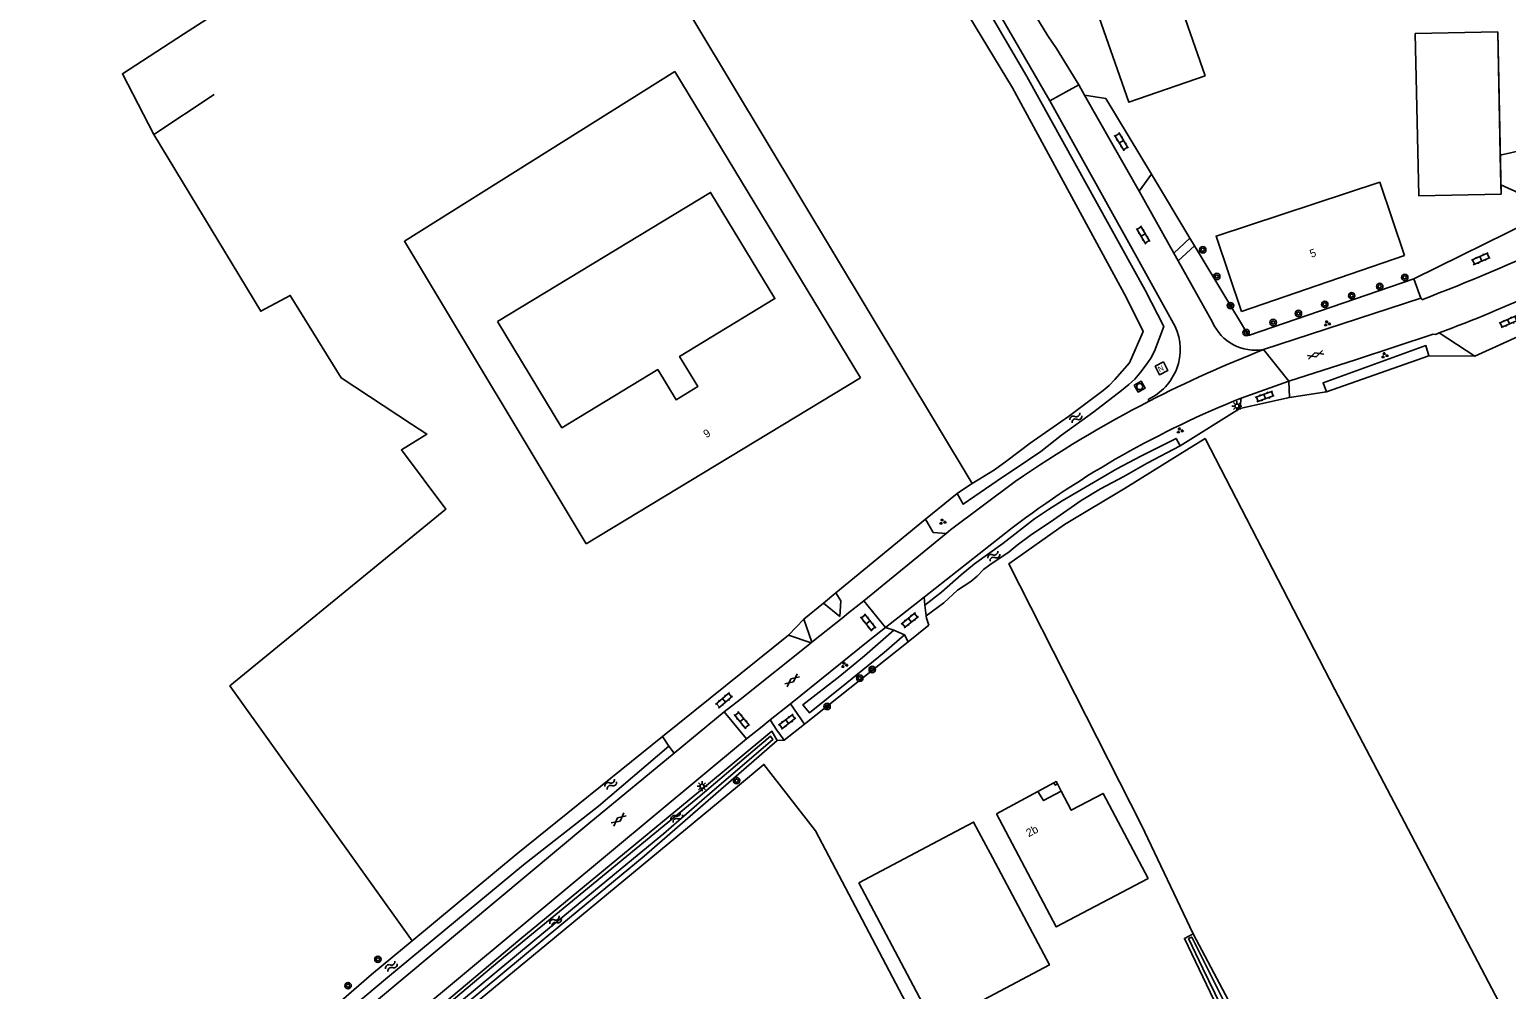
# Model space of a CAD drawing. Extents: x 135999 to 138000, y 396000 to 398501.
# Drawn here: x 136699.2 to 136883.8, y 396981.4 to 397101.4 of the extents above; entities that cross this region are included whole.
import ezdxf

# ---------------------------------------------------------------- set-up
doc = ezdxf.new("R2010")
doc.units = 0
for name, color, linetype in [('gg-afsc-draadraster', 7, 'Continuous'), ('gg-afsc-hekwerk', 7, 'Continuous'), ('gg-afsc-lijn draadraster', 7, 'Continuous'), ('gg-afsc-muur', 7, 'Continuous'), ('gg-anno-huisnummerreeks BGT', 7, 'Continuous'), ('gg-bbg-bijgebouw', 7, 'Continuous'), ('gg-bbg-gedigitaliseerde bebouwing', 7, 'Continuous'), ('gg-bbg-gedigitaliseerde bijgebouw', 7, 'Continuous'), ('gg-bbg-hoofdgebouw', 7, 'Continuous'), ('gg-bbg-onder overbouw', 7, 'Continuous'), ('gg-bbg-pand overbouw', 7, 'Continuous'), ('gg-bbg-pilaar onder overbouw', 7, 'Continuous'), ('gg-bbg-pilaar pand', 7, 'Continuous'), ('gg-knt-bronhoudergrens', 7, 'Continuous'), ('gg-knt-onverhard', 7, 'Continuous'), ('gg-knt-verharding', 7, 'Continuous'), ('gg-knt-verharding nz', 7, 'Continuous'), ('gg-kntw-bovenkant insteek waterloop', 7, 'Continuous'), ('gg-kntw-waterlijn', 7, 'Continuous'), ('gt-grn-groengrens', 7, 'Continuous'), ('gt-grn-vlakafsluiter', 7, 'Continuous'), ('gt-grn-weggrens', 7, 'Continuous'), ('gt-symb-boom', 7, 'Continuous'), ('gt-symb-gesloten verharding', 7, 'Continuous'), ('gt-symb-groenvak', 7, 'Continuous'), ('gt-symb-klinker verharding', 7, 'Continuous'), ('gt-symb-lichtmast', 7, 'Continuous'), ('gt-symb-nortonput', 7, 'Continuous'), ('gt-symb-rioolschacht', 7, 'Continuous'), ('gt-symb-watersymbool', 7, 'Continuous'), ('gx-grn-BAG pand plantopografie verbouwing', 7, 'Continuous'), ('gx-grn-maaiveld', 7, 'Continuous')]:
    doc.layers.add(name, color=color, linetype=linetype)

# ---------------------------------------------------------------- blocks, each defined once
blk = doc.blocks.new('gt0-KL1')
at = {"layer": 'gt-symb-klinker verharding'}
for p, q in [((-1.15, 0.3), (1.15, 0.3)), ((-1, -0.3), (-1, 0.3)), ((-0.5, 0.3), (-0.5, 0.45)), ((0, -0.3), (0, 0.3)), ((0.5, 0.3), (0.5, 0.45)), ((1, -0.3), (1, 0.3)), ((-1.15, -0.3), (1.15, -0.3)), ((-0.5, -0.45), (-0.5, -0.3)), ((0.5, -0.45), (0.5, -0.3))]:
    blk.add_line(p, q, dxfattribs=at)
blk = doc.blocks.new('gt0-BOOM')
at = {"layer": 'gt-symb-boom'}
for radius in [0.4, 0.2]:
    blk.add_circle((0, 0), radius, dxfattribs=at)
blk = doc.blocks.new('gt0-RS')
at = {"layer": 'gt-symb-rioolschacht'}
blk.add_lwpolyline([(-0.5, -0.5), (0.5, -0.5), (0.5, 0.5), (-0.5, 0.5)], close=True, dxfattribs=at)
blk.add_circle((0, 0), 0.375, dxfattribs=at)
blk = doc.blocks.new('gt0-NPUT')
at = {"layer": 'gt-symb-nortonput'}
blk.add_lwpolyline([(-0.57, -0.61), (-0.57, 0.59), (0.63, 0.59), (0.63, -0.61)], close=True, dxfattribs=at)
blk.add_text('N', height=0.7, dxfattribs=at).set_placement((-0.22, -0.38))
blk = doc.blocks.new('gt0-GESVH1')
at = {"layer": 'gt-symb-gesloten verharding'}
for p, q in [((-0.99, -0.26), (0.01, 0.24)), ((0.01, -0.26), (-0.99, 0.24)), ((0.01, 0.24), (1.01, -0.26)), ((1.01, 0.24), (0.01, -0.26))]:
    blk.add_line(p, q, dxfattribs=at)
blk = doc.blocks.new('gt0-GRVAK')
at = {"layer": 'gt-symb-groenvak'}
for p, q in [((-0.11, 0.19), (-0.23, 0.24)), ((-0.18, 0.15), (0.09, 0.15)), ((-0.09, 0.21), (-0.16, 0.32)), ((-0.05, 0.21), (-0.05, 0.39)), ((0, 0.21), (0.06, 0.32)), ((0.02, 0.19), (0.13, 0.24)), ((0.26, -0.05), (0.2, 0.06)), ((0.3, -0.05), (0.3, 0.13)), ((0.35, -0.05), (0.41, 0.06)), ((-0.24, -0.23), (-0.36, -0.18)), ((-0.32, -0.26), (-0.05, -0.26)), ((-0.23, -0.21), (-0.29, -0.1)), ((-0.18, -0.2), (-0.18, -0.02)), ((-0.14, -0.21), (-0.07, -0.1)), ((-0.12, -0.23), (0, -0.18)), ((0.24, -0.07), (0.12, -0.02)), ((0.17, -0.11), (0.44, -0.11)), ((0.37, -0.07), (0.49, -0.02))]:
    blk.add_line(p, q, dxfattribs=at)
blk = doc.blocks.new('gt0-WA')
at = {"layer": 'gt-symb-watersymbool'}
for centre, start, end in [((-0.32, 0.02), 28.0725, 151.9275), ((0.43, 0.42), 208.0725, 331.9275), ((-0.32, -0.43), 28.0725, 151.9275), ((0.43, -0.03), 208.0725, 331.9275)]:
    blk.add_arc(centre, 0.425, start, end, dxfattribs=at)
blk = doc.blocks.new('gt0-LMAST')
at = {"layer": 'gt-symb-lichtmast'}
for p, q in [((-0.18, 0.17), (-0.45, 0.44)), ((-0.01, 0.25), (-0.01, 0.62)), ((0.17, 0.17), (0.44, 0.44)), ((-0.26, 0), (-0.63, 0)), ((-0.18, -0.18), (-0.45, -0.45)), ((-0.01, -0.25), (-0.01, -0.63)), ((0.44, -0.45), (0.17, -0.18)), ((0.24, 0), (0.62, 0))]:
    blk.add_line(p, q, dxfattribs=at)
blk.add_circle((-0.01, 0), 0.25, dxfattribs=at)

msp = doc.modelspace()

# ---------------------------------------------------------------- linework, layer by layer
at = {"layer": 'gg-afsc-draadraster'}
for points in [[(136842.96, 397048.32), (136836.15, 397044.09), (136828.54, 397039.55), (136821.58, 397034.63), (136838.19, 397001.98), (136844.64, 396988.38)], [(136787.67, 397006.79), (136763.83, 396987.1), (136739.79, 396967.26)]]:
    msp.add_lwpolyline(points, dxfattribs=at)
at = {"layer": 'gg-afsc-hekwerk'}
for p, q in [((136808.99, 397024.87), (136811.61, 397026.96)), ((136808.99, 397024.87), (136811.61, 397026.96)), ((136796.06, 397014.6), (136808.99, 397024.87)), ((136796.06, 397014.6), (136808.99, 397024.87)), ((136793.51, 397012.58), (136796.06, 397014.6)), ((136793.51, 397012.58), (136796.06, 397014.6))]:
    msp.add_line(p, q, dxfattribs=at)
at = {"layer": 'gg-afsc-lijn draadraster'}
msp.add_line((136883.71, 396978.2), (136862.33, 397018.93), dxfattribs=at)
for points in [[(136747.02, 396987.51), (136724.24, 397019.37), (136751.23, 397041.47), (136745.67, 397048.87), (136748.85, 397050.86), (136746.92, 397052.07), (136738.13, 397057.87), (136731.78, 397068.19), (136728.08, 397066.2), (136714.71, 397088.3), (136722.26, 397093.32)], [(136842.96, 397048.32), (136836.15, 397044.09), (136828.54, 397039.55), (136821.58, 397034.63), (136838.19, 397001.98), (136844.64, 396988.38)], [(136787.67, 397006.79), (136763.83, 396987.1), (136739.79, 396967.26)]]:
    msp.add_lwpolyline(points, dxfattribs=at)
at = {"layer": 'gg-afsc-muur'}
for p, q in [((136844.21, 397075.36), (136839.41, 397083.33)), ((136844.79, 397074.4), (136844.21, 397075.36)), ((136845.12, 397073.85), (136844.79, 397074.4))]:
    msp.add_line(p, q, dxfattribs=at)
at = {"layer": 'gg-bbg-bijgebouw'}
for p, q in [((136802.85, 396994.75), (136812.76, 397000)), ((136819.53, 396997.93), (136818.43, 397000))]:
    msp.add_line(p, q, dxfattribs=at)
for points in [[(136821.73, 397134.87), (136836.58, 397092.33), (136846.14, 397095.65)], [(136812.76, 397000), (136817.19, 397002.35), (136818.43, 397000)], [(136802.85, 396994.75), (136812.32, 396976.88), (136826.66, 396984.48), (136819.53, 396997.93)]]:
    msp.add_lwpolyline(points, dxfattribs=at)
at = {"layer": 'gg-bbg-gedigitaliseerde bebouwing'}
msp.add_line((136779.86, 397096.17), (136803.04, 397057.88), dxfattribs=at)
for points in [[(136768.76, 397037.15), (136746.04, 397074.96), (136779.86, 397096.17)], [(136757.67, 397064.94), (136765.72, 397051.65), (136777.71, 397058.91), (136779.99, 397055.15), (136782.72, 397056.8), (136780.44, 397060.57), (136792.36, 397067.79), (136784.31, 397081.07), (136757.67, 397064.94)], [(136871.04, 397073.17), (136867.96, 397082.33), (136847.5, 397075.61), (136850.66, 397066.18)], [(136839, 396995.31), (136827.52, 396989.24), (136820.03, 397003.38)]]:
    msp.add_lwpolyline(points, dxfattribs=at)
at = {"layer": 'gg-bbg-gedigitaliseerde bijgebouw'}
msp.add_lwpolyline([(136846.14, 397095.65), (136831.29, 397138.2), (136821.73, 397134.87)], dxfattribs=at)
at = {"layer": 'gg-bbg-hoofdgebouw'}
for p, q in [((136871.04, 397073.17), (136850.66, 397066.18)), ((136803.04, 397057.88), (136768.76, 397037.15)), ((136825.22, 397006.16), (136820.03, 397003.38))]:
    msp.add_line(p, q, dxfattribs=at)
msp.add_lwpolyline([(136839, 396995.31), (136833.38, 397005.92), (136829.4, 397003.83), (136828.13, 397006.23)], dxfattribs=at)
at = {"layer": 'gg-bbg-onder overbouw'}
msp.add_lwpolyline([(136828.13, 397006.23), (136825.93, 397005.04), (136825.22, 397006.16)], dxfattribs=at)
at = {"layer": 'gg-bbg-pand overbouw'}
for p, q in [((136827.23, 397007.25), (136825.22, 397006.16)), ((136827.67, 397007.12), (136828.13, 397006.23))]:
    msp.add_line(p, q, dxfattribs=at)
at = {"layer": 'gg-bbg-pilaar onder overbouw'}
msp.add_lwpolyline([(136827.23, 397007.25), (136827.39, 397006.97), (136827.67, 397007.12)], dxfattribs=at)
at = {"layer": 'gg-bbg-pilaar pand'}
msp.add_lwpolyline([(136827.67, 397007.12), (136827.52, 397007.4), (136827.23, 397007.25)], dxfattribs=at)
at = {"layer": 'gg-knt-bronhoudergrens'}
for p, q in [((136846.12, 397050.28), (136842.96, 397048.32)), ((136862.33, 397018.93), (136846.12, 397050.28))]:
    msp.add_line(p, q, dxfattribs=at)
msp.add_lwpolyline([(136815.4, 396967.75), (136812.15, 396973.03), (136809.55, 396978.2), (136797.44, 397001.25), (136790.97, 397009.55), (136787.67, 397006.79)], dxfattribs=at)
at = {"layer": 'gg-knt-onverhard'}
msp.add_line((136826.7, 397092.51), (136817.92, 397107.73), dxfattribs=at)
msp.add_lwpolyline([(136809.49, 397129.77), (136817.67, 397115.5), (136825.43, 397102.33), (136826.47, 397100.63), (136827.56, 397099.06), (136830.33, 397094.52)], dxfattribs=at)
at = {"layer": 'gg-knt-verharding'}
for p, q in [((136826.7, 397092.51), (136830.33, 397094.52)), ((136837.21, 397073.62), (136826.7, 397092.51)), ((136837.89, 397081.22), (136839.41, 397083.33)), ((136837.89, 397081.22), (136842.22, 397073.47)), ((136872.23, 397070.24), (136886.9, 397077.53)), ((136844.21, 397075.36), (136842.22, 397073.47)), ((136837.21, 397073.62), (136842.39, 397064.29)), ((136842.22, 397073.47), (136842.77, 397072.49)), ((136844.79, 397074.4), (136842.77, 397072.49)), ((136842.77, 397072.49), (136847.05, 397064.83)), ((136873.08, 397067.84), (136872.23, 397070.24)), ((136853.44, 397061.41), (136873.08, 397067.84)), ((136879.82, 397060.58), (136875.38, 397063.49)), ((136856.58, 397057.48), (136850.64, 397055.35)), ((136856.58, 397057.48), (136856.67, 397055.41)), ((136839.14, 397054.97), (136838.99, 397055.18)), ((136850.47, 397054.04), (136856.67, 397055.41)), ((136850.64, 397055.35), (136850.47, 397054.04)), ((136811.18, 397040.2), (136799.97, 397030.99)), ((136803.47, 397030.02), (136813.75, 397038.44)), ((136822.02, 397039.13), (136810.99, 397030.46)), ((136800.48, 397028.06), (136798.42, 397029.72)), ((136803.47, 397030.02), (136801.56, 397028.5)), ((136803.47, 397030.02), (136806.16, 397026.66)), ((136810.99, 397030.46), (136806.16, 397026.66)), ((136811.1, 397029.46), (136810.99, 397030.46)), ((136811.25, 397028.12), (136811.1, 397029.46)), ((136795.96, 397027.71), (136796.97, 397024.84)), ((136800.75, 397027.85), (136796.97, 397024.84)), ((136801.56, 397028.5), (136800.75, 397027.85)), ((136794.04, 397025.7), (136796.89, 397024.77)), ((136806.16, 397026.66), (136804.23, 397025.11)), ((136807.21, 397026.32), (136806.16, 397026.66)), ((136808.54, 397025.77), (136807.21, 397026.32)), ((136808.99, 397024.87), (136808.54, 397025.77)), ((136796.89, 397024.77), (136788, 397017.69)), ((136804.23, 397025.11), (136794.29, 397017.14)), ((136796.97, 397024.84), (136796.89, 397024.77)), ((136788, 397017.69), (136786.03, 397016.12)), ((136794.29, 397017.14), (136791.78, 397015.13)), ((136794.29, 397017.14), (136796.06, 397014.6)), ((136786.03, 397016.12), (136779.77, 397010.95)), ((136786.03, 397016.12), (136788.8, 397012.74)), ((136790.77, 397014.31), (136788.8, 397012.74)), ((136791.78, 397015.13), (136790.77, 397014.31)), ((136779.08, 397011.83), (136778.3, 397013.04)), ((136779.08, 397011.83), (136779.77, 397010.95))]:
    msp.add_line(p, q, dxfattribs=at)
for points in [[(136873.08, 397067.84), (136873.15, 397067.86), (136873.23, 397067.66)], [(136887.64, 397067.29), (136886.53, 397063.62), (136879.82, 397060.58)], [(136813.75, 397038.44), (136814.28, 397038.88), (136822.39, 397044.93)], [(136813.75, 397038.44), (136812.15, 397038.55), (136811.18, 397040.2)], [(136799.97, 397030.99), (136800.58, 397030.01), (136800.48, 397028.06)], [(136811.61, 397026.96), (136811.28, 397027.83), (136811.25, 397028.12)], [(136793.51, 397012.58), (136792.61, 397013.84), (136791.78, 397015.13)], [(136788.8, 397012.74), (136771.69, 396998.51), (136747.35, 396978.24)], [(136779.77, 397010.95), (136769.1, 397002.15), (136738.25, 396976.43), (136729.99, 396969.4), (136729.71, 396969.33), (136723.7, 396964.14), (136723.46, 396963.64), (136696.05, 396939.83)]]:
    msp.add_lwpolyline(points, dxfattribs=at)
for centre, radius, start, end in [((136789.38, 397288.34), 236.08, 290.8026, 295.3307), ((136817.01, 397220.7), 167.69, 290.3687, 295.0412), ((136836.14, 397061.44), 6.87, 294.527, 24.5554), ((136852.43, 397067.21), 5.88, 203.8681, 279.8464), ((136907.87, 396921.42), 150.2, 111.2469, 117.2316), ((136895.99, 396941.97), 122.11, 111.799, 127.2803), ((136907.91, 396921.33), 150.29, 117.2301, 124.6783)]:
    msp.add_arc(centre, radius, start, end, dxfattribs=at)
at = {"layer": 'gg-knt-verharding nz'}
for p, q in [((136830.33, 397094.52), (136831.06, 397093.24)), ((136831.06, 397093.24), (136837.89, 397081.22))]:
    msp.add_line(p, q, dxfattribs=at)
at = {"layer": 'gg-kntw-bovenkant insteek waterloop'}
for p, q in [((136760.03, 396998.29), (136778.3, 397013.04)), ((136760.03, 396998.29), (136747.21, 396987.67)), ((136747.21, 396987.67), (136747.02, 396987.51))]:
    msp.add_line(p, q, dxfattribs=at)
for points in [[(136798.83, 397132.34), (136801.28, 397133.82), (136812.55, 397114.88), (136823.86, 397095.54), (136838.62, 397068.83), (136840.95, 397064.28), (136839.79, 397061.23)], [(136839.79, 397061.23), (136839.33, 397060.35), (136838.77, 397059.52), (136837.98, 397058.46), (136837.33, 397057.71), (136836.61, 397057.03), (136835.69, 397056.29), (136832.22, 397053.64), (136828.19, 397050.71), (136825.58, 397048.69), (136823.94, 397047.55), (136820.12, 397045), (136815.9, 397042.07), (136815.12, 397043.44)], [(136817.02, 397044.66), (136819.79, 397046.39), (136821.36, 397047.49), (136824.27, 397049.7), (136829.04, 397053.03), (136833.4, 397056.28), (136834.15, 397056.93), (136834.85, 397057.66), (136836.66, 397059.74)], [(136811.1, 397029.46), (136813.16, 397031.08), (136815.65, 397033.27), (136817.32, 397034.65), (136820.85, 397037.17), (136824.79, 397040.24), (136826.56, 397041.44), (136828.26, 397042.49), (136835.1, 397046.49), (136838.1, 397048.1), (136842.49, 397050.3), (136843, 397049.4)], [(136843, 397049.4), (136838.88, 397047.23), (136835.96, 397045.56), (136833.03, 397044), (136830.65, 397042.54), (136827.19, 397040.12), (136824.24, 397038.17), (136822.64, 397036.97), (136821.64, 397036.11), (136819.21, 397034.52), (136818.42, 397033.94), (136817.63, 397033.09), (136816.83, 397032.44), (136815.19, 397031.35), (136813.46, 397029.75), (136811.25, 397028.12)], [(136815.12, 397043.44), (136816.43, 397044.3), (136817.02, 397044.66)], [(136808.54, 397025.77), (136805.99, 397023.56), (136801.36, 397019.75), (136796.66, 397016.01), (136795.85, 397017.01), (136800.45, 397020.6), (136803.55, 397023.13), (136807.21, 397026.32)], [(136743.58, 396971.21), (136765.71, 396989.58), (136776.02, 396998.1), (136792.64, 397012.56)], [(136792.64, 397012.56), (136791.98, 397013.7), (136783.07, 397006.28), (136760.46, 396987.68)], [(136760.94, 396996.98), (136770.3, 397004.35), (136779.08, 397011.83)], [(136727.74, 396970.97), (136728.47, 396969.94), (136743.91, 396982.93), (136760.94, 396996.98)], [(136747.02, 396987.51), (136741.94, 396983.31), (136727.74, 396970.97)], [(136760.46, 396987.68), (136742.44, 396972.51), (136743.58, 396971.21)], [(136844.64, 396988.38), (136843.53, 396987.81), (136847.22, 396980.11)]]:
    msp.add_lwpolyline(points, dxfattribs=at)
at = {"layer": 'gg-kntw-waterlijn'}
for points in [[(136743.18, 396972.59), (136757.71, 396984.84), (136782.71, 397005.37), (136791.8, 397013.09), (136792.08, 397012.66), (136784.17, 397005.86), (136778.43, 397000.86), (136773.26, 396996.63), (136762.28, 396987.52), (136743.61, 396972.03), (136743.18, 396972.59)], [(136862.69, 396949.06), (136863.06, 396949.53), (136862.81, 396950.43), (136861.45, 396953.32), (136860.21, 396955.56), (136849.53, 396976.4), (136845.85, 396984.06), (136844.06, 396987.78), (136844.46, 396987.97), (136848.9, 396979.11), (136855.53, 396965.92), (136862.53, 396952.68), (136863.75, 396950.01), (136863.65, 396949.17), (136862.95, 396948.38)]]:
    msp.add_lwpolyline(points, dxfattribs=at)
at = {"layer": 'gt-grn-groengrens'}
for p, q in [((136874.08, 397060.64), (136861.3, 397056.13)), ((136874.08, 397060.64), (136879.82, 397060.58)), ((136856.67, 397055.41), (136861.3, 397056.13)), ((136843, 397049.4), (136850.47, 397054.04)), ((136811.18, 397040.2), (136815.12, 397043.44)), ((136798.42, 397029.72), (136799.97, 397030.99)), ((136795.96, 397027.71), (136794.04, 397025.7)), ((136792.64, 397012.56), (136793.51, 397012.58))]:
    msp.add_line(p, q, dxfattribs=at)
for points in [[(136845.12, 397073.85), (136851.53, 397063.19), (136872.23, 397070.24)], [(136861.3, 397056.13), (136860.86, 397057.26), (136873.73, 397061.91), (136874.08, 397060.64)]]:
    msp.add_lwpolyline(points, dxfattribs=at)
at = {"layer": 'gt-grn-vlakafsluiter'}
msp.add_line((136794.04, 397025.7), (136778.3, 397013.04), dxfattribs=at)
at = {"layer": 'gt-grn-weggrens'}
for p, q in [((136833.72, 397092.8), (136831.06, 397093.24)), ((136839.41, 397083.33), (136833.72, 397092.8)), ((136856.58, 397057.48), (136853.44, 397061.41)), ((136795.96, 397027.71), (136798.42, 397029.72))]:
    msp.add_line(p, q, dxfattribs=at)
at = {"layer": 'gx-grn-BAG pand plantopografie verbouwing'}
msp.add_line((136883.12, 397080.86), (136882.7, 397101.15), dxfattribs=at)
at = {"layer": 'gx-grn-maaiveld'}
for p, q in [((136883.02, 397085.71), (136882.7, 397101.15)), ((136883.02, 397085.71), (136883.1, 397082.01)), ((136883.1, 397082.01), (136883.12, 397080.86)), ((136883.71, 396978.2), (136862.33, 397018.93)), ((136844.64, 396988.38), (136858.3, 396962.57))]:
    msp.add_line(p, q, dxfattribs=at)
for points in [[(136883.02, 397085.71), (136891.86, 397087.73), (136890.98, 397104.47), (136879.95, 397104.23), (136888.02, 397111.35), (136918.91, 397136.11), (136942.25, 397155.01), (136950.14, 397160.65)], [(136747.02, 396987.51), (136724.24, 397019.37), (136751.23, 397041.47), (136745.67, 397048.87), (136748.85, 397050.86), (136746.92, 397052.07), (136738.13, 397057.87), (136731.78, 397068.19), (136728.08, 397066.2), (136714.71, 397088.3), (136710.79, 397095.9), (136718.42, 397100.86), (136760.71, 397128.09), (136765.38, 397130.62), (136817.02, 397044.66)], [(136812.79, 397109.44), (136822.06, 397094.13), (136836.3, 397067.89), (136838.37, 397063.69), (136836.66, 397059.74)], [(136883.12, 397080.86), (136872.82, 397080.65), (136872.4, 397100.93), (136882.7, 397101.15)], [(136883.1, 397082.01), (136885.77, 397080.79), (136885.87, 397079.1), (136888.51, 397076.63)], [(136856.58, 397057.48), (136865.05, 397060.17), (136874.62, 397063.35), (136874.88, 397063.31)], [(136874.88, 397063.31), (136875.12, 397063.4), (136875.38, 397063.49)]]:
    msp.add_lwpolyline(points, dxfattribs=at)

# ---------------------------------------------------------------- block references
at = {"layer": 'gt-symb-boom'}
for p in [(136845.83, 397073.89), (136847.58, 397070.55), (136867.95, 397069.31), (136871.08, 397070.44), (136864.44, 397068.15), (136849.3, 397066.91), (136857.79, 397065.93), (136861.08, 397067.07), (136854.63, 397064.8), (136851.25, 397063.54), (136804.52, 397021.42), (136802.96, 397020.34), (136798.88, 397016.8), (136787.56, 397007.53), (136742.73, 396985.19), (136739, 396981.89)]:
    msp.add_blockref('gt0-BOOM', p, dxfattribs=at)
at = {"layer": 'gt-symb-gesloten verharding'}
for p, rotation in [((136859.92, 397060.76), 18.12681251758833), ((136794.5, 397020.06), 39.196688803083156), ((136772.82, 397002.67), 39.196688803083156)]:
    msp.add_blockref('gt0-GESVH1', p, dxfattribs=dict(at, rotation=rotation))
at = {"layer": 'gt-symb-groenvak'}
for p in [(136861.36, 397064.67), (136868.55, 397060.69), (136842.96, 397051.29), (136813.3, 397039.88), (136801.03, 397021.98)]:
    msp.add_blockref('gt0-GRVAK', p, dxfattribs=at)
at = {"layer": 'gt-symb-klinker verharding'}
for p, rotation in [((136835.66, 397087.41), -58.918270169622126), ((136838.38, 397075.74), -58.99693247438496), ((136880.58, 397072.76), 23.386642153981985), ((136884.06, 397064.9), -156.17710051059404), ((136853.57, 397055.55), -159.75249849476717), ((136804.01, 397027.3), 128.25701687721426), ((136809.22, 397027.58), 38.5434627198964), ((136785.99, 397017.57), 40.53915174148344), ((136788.23, 397015.1), -50.64204308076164), ((136793.89, 397014.9), 37.31697448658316)]:
    msp.add_blockref('gt0-KL1', p, dxfattribs=dict(at, rotation=rotation))
at = {"layer": 'gt-symb-lichtmast'}
for p in [(136850.11, 397054.36), (136783.25, 397006.82)]:
    msp.add_blockref('gt0-LMAST', p, dxfattribs=at)
at = {"layer": 'gt-symb-nortonput', "rotation": -153.1274610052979}
msp.add_blockref('gt0-NPUT', (136840.7, 397059.07), dxfattribs=at)
at = {"layer": 'gt-symb-rioolschacht', "rotation": -60.66720921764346}
msp.add_blockref('gt0-RS', (136837.95, 397056.78), dxfattribs=at)
at = {"layer": 'gt-symb-watersymbool'}
for p, rotation in [((136829.92, 397052.85), 35.724134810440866), ((136819.67, 397035.56), 35.64420015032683), ((136771.79, 397007.05), 38.46294706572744), ((136780.03, 397002.91), 38.46294706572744), ((136764.89, 396989.92), 39.724862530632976), ((136744.37, 396984.29), 40.091680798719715)]:
    msp.add_blockref('gt0-WA', p, dxfattribs=dict(at, rotation=rotation))

# ---------------------------------------------------------------- texts
at = {"layer": 'gg-anno-huisnummerreeks BGT'}
for s, rotation, p in [('5', 18.9, (136859.4, 397072.88)), ('9', 31.1, (136783.78, 397050.32)), ('2b', 28.2, (136824.07, 397000.44))]:
    msp.add_text(s, height=1, rotation=rotation, dxfattribs=at).set_placement(p)

doc.saveas('drawing.dxf')
